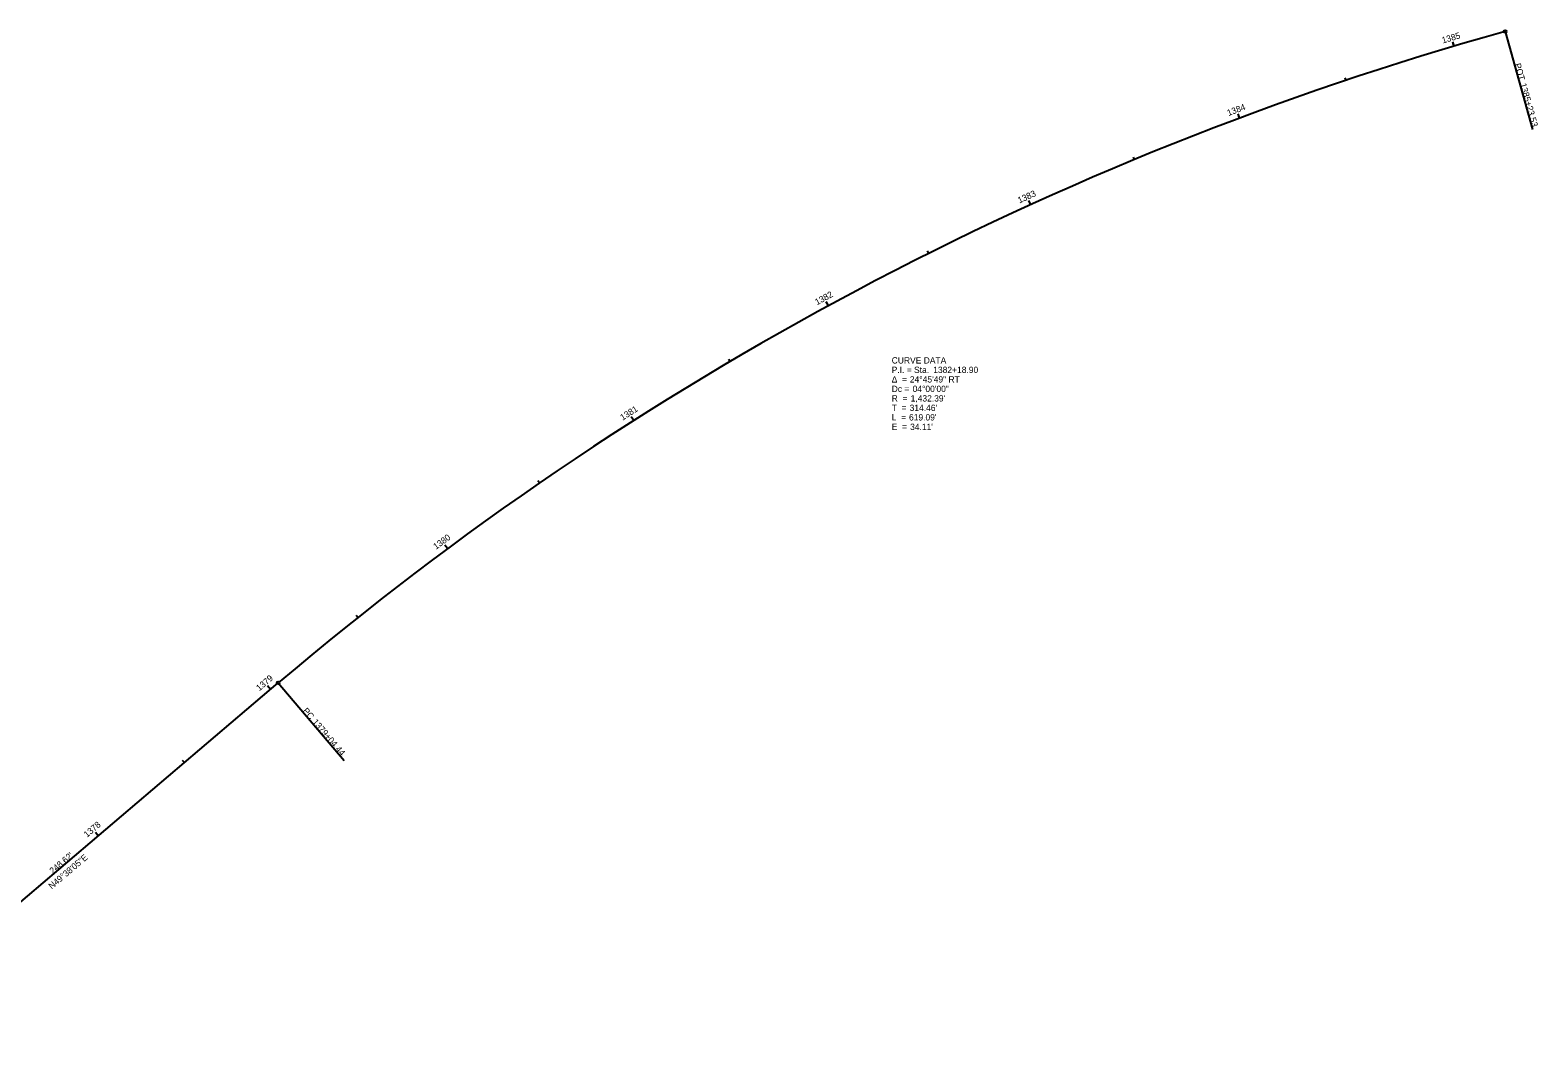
# Model space of a CAD drawing. Extents: x 155009 to 156350, y 371331 to 371956.
# Drawn here: x 155684 to 156350, y 371506 to 371956 of the extents above; entities that cross this region are included whole.
import ezdxf

# ---------------------------------------------------------------- set-up
doc = ezdxf.new("R2010")
doc.units = 0
for name, color, linetype in [('Default', 7, 'Continuous'), ('GE_X_Alignment', 7, 'Continuous'), ('GE_X_Alignment_1000_Curve_Data', 7, 'Continuous'), ('GE_X_Alignment_1000_Stations', 7, 'Continuous'), ('GE_X_Alignment_100_Curve_Data', 7, 'Continuous'), ('GE_X_Alignment_100_Stations', 7, 'Continuous'), ('GE_X_Alignment_500_Curve_Data', 7, 'Continuous'), ('GE_X_Alignment_500_Stations', 7, 'Continuous')]:
    doc.layers.add(name, color=color, linetype=linetype)

msp = doc.modelspace()

# ---------------------------------------------------------------- linework, layer by layer
at = {"layer": 'Default'}
msp.add_arc((156721.25, 370575.5), 1432.39, 105.6015, 130.36518, dxfattribs=at)
at = {"layer": 'GE_X_Alignment'}
msp.add_line((155604.12, 371505.86), (155793.55, 371666.88), dxfattribs=at)
msp.add_arc((156721.25, 370575.5), 1432.39, 105.6015, 130.36518, dxfattribs=at)
at = {"layer": 'GE_X_Alignment_1000_Stations'}
for p, q in [((156336.01, 371955.11), (156348.12, 371911.77)), ((156313.4, 371948.6), (156313.06, 371949.75)), ((155868.37, 371726.3), (155867.18, 371727.9)), ((155793.55, 371666.88), (155822.69, 371632.59))]:
    msp.add_line(p, q, dxfattribs=at)
for centre in [(156336.01, 371955.11), (155793.55, 371666.88)]:
    msp.add_circle(centre, 0.6, dxfattribs=at)
at = {"layer": 'GE_X_Alignment_100_Stations'}
for p, q in [((156336.01, 371955.11), (156348.12, 371911.77)), ((156313.4, 371948.6), (156312.83, 371950.51)), ((156265.73, 371933.53), (156265.35, 371934.66)), ((156218.61, 371916.8), (156217.91, 371918.68)), ((156172.11, 371898.44), (156171.65, 371899.55)), ((156126.27, 371878.47), (156125.44, 371880.29)), ((156081.16, 371856.92), (156080.63, 371857.99)), ((156036.83, 371833.8), (156035.88, 371835.55)), ((155993.33, 371809.14), (155992.72, 371810.18)), ((155950.72, 371782.99), (155949.65, 371784.67)), ((155909.05, 371755.36), (155908.37, 371756.35)), ((155868.37, 371726.3), (155867.18, 371727.9)), ((155828.73, 371695.83), (155827.98, 371696.77)), ((155793.55, 371666.88), (155822.69, 371632.59)), ((155790.17, 371664.01), (155788.87, 371665.53)), ((155752.07, 371631.62), (155751.29, 371632.54)), ((155713.97, 371599.24), (155712.68, 371600.76))]:
    msp.add_line(p, q, dxfattribs=at)
for centre in [(156336.01, 371955.11), (155793.55, 371666.88)]:
    msp.add_circle(centre, 0.6, dxfattribs=at)
at = {"layer": 'GE_X_Alignment_500_Stations'}
for p, q in [((156336.01, 371955.11), (156348.12, 371911.77)), ((156313.4, 371948.6), (156312.83, 371950.51)), ((156218.61, 371916.8), (156218.19, 371917.93)), ((156126.27, 371878.47), (156125.77, 371879.56)), ((156036.83, 371833.8), (156036.26, 371834.85)), ((155950.72, 371782.99), (155950.08, 371784)), ((155868.37, 371726.3), (155867.18, 371727.9)), ((155793.55, 371666.88), (155822.69, 371632.59)), ((155790.17, 371664.01), (155789.39, 371664.92)), ((155713.97, 371599.24), (155713.2, 371600.15))]:
    msp.add_line(p, q, dxfattribs=at)
for centre in [(156336.01, 371955.11), (155793.55, 371666.88)]:
    msp.add_circle(centre, 0.6, dxfattribs=at)

# ---------------------------------------------------------------- texts
at = {"layer": 'GE_X_Alignment_1000_Curve_Data'}
for s, p in [('CURVE DATA', (156064.78, 371808.2)), ('P.I. = Sta. ', (156064.78, 371804)), ('1382+18.90', (156083.15, 371804)), ('Δ  = ', (156064.78, 371799.8)), ('24°45\'49" RT', (156072.8, 371799.8)), ('Dc = ', (156064.78, 371795.6)), ('R  = ', (156064.78, 371791.4)), ("1,432.39'", (156073.15, 371791.4)), ('04°00\'00"', (156074.02, 371795.6)), ('T  = ', (156064.78, 371787.2)), ("314.46'", (156072.71, 371787.2)), ('L  = ', (156064.78, 371783)), ('E  = ', (156064.78, 371778.8)), ("619.09'", (156072.43, 371783)), ("34.11'", (156072.93, 371778.8))]:
    msp.add_text(s, height=2.8, dxfattribs=at).set_placement(p)
at = {"layer": 'GE_X_Alignment_1000_Stations'}
for s, rotation, p in [('POT', 285.6015, (156340.11, 371940.63)), ('1385+23.53', 285.6015, (156342.56, 371931.84)), ('1380', 36.54276, (155863.34, 371725.74)), ('PC', 310.36518, (155804.19, 371654.43)), ('1379+04.44', 310.36518, (155808.42, 371649.46)), ('N49°38\'05"E', 40.36518, (155693.42, 371575.47)), ("248.62'", 40.36518, (155693.86, 371582.21))]:
    msp.add_text(s, height=2.8, rotation=rotation, dxfattribs=at).set_placement(p)
at = {"layer": 'GE_X_Alignment_100_Curve_Data'}
for s, p in [('CURVE DATA', (156064.78, 371808.2)), ('P.I. = Sta. ', (156064.78, 371804)), ('1382+18.90', (156083.15, 371804)), ('Δ  = ', (156064.78, 371799.8)), ('24°45\'49" RT', (156072.8, 371799.8)), ('Dc = ', (156064.78, 371795.6)), ('R  = ', (156064.78, 371791.4)), ("1,432.39'", (156073.15, 371791.4)), ('04°00\'00"', (156074.02, 371795.6)), ('T  = ', (156064.78, 371787.2)), ("314.46'", (156072.71, 371787.2)), ('L  = ', (156064.78, 371783)), ('E  = ', (156064.78, 371778.8)), ("619.09'", (156072.43, 371783)), ("34.11'", (156072.93, 371778.8))]:
    msp.add_text(s, height=2.8, dxfattribs=at).set_placement(p)
at = {"layer": 'GE_X_Alignment_100_Stations'}
for s, rotation, p in [('1385', 16.5427, (156308.48, 371949.79)), ('POT', 285.6015, (156340.11, 371940.63)), ('1385+23.53', 285.6015, (156342.56, 371931.84)), ('1384', 20.54271, (156213.67, 371917.67)), ('1383', 24.54273, (156121.26, 371878.98)), ('1382', 28.54274, (156031.78, 371833.95)), ('1381', 32.54275, (155945.81, 371782.88)), ('1380', 36.54276, (155863.34, 371725.74)), ('1379', 40.36518, (155785.21, 371663.14)), ('PC', 310.36518, (155804.19, 371654.43)), ('1379+04.44', 310.36518, (155808.42, 371649.46)), ('1378', 40.36518, (155709, 371598.35)), ('N49°38\'05"E', 40.36518, (155693.42, 371575.47)), ("248.62'", 40.36518, (155693.86, 371582.21))]:
    msp.add_text(s, height=2.8, rotation=rotation, dxfattribs=at).set_placement(p)
at = {"layer": 'GE_X_Alignment_500_Curve_Data'}
for s, p in [('CURVE DATA', (156064.78, 371808.2)), ('P.I. = Sta. ', (156064.78, 371804)), ('1382+18.90', (156083.15, 371804)), ('Δ  = ', (156064.78, 371799.8)), ('24°45\'49" RT', (156072.8, 371799.8)), ('Dc = ', (156064.78, 371795.6)), ('R  = ', (156064.78, 371791.4)), ("1,432.39'", (156073.15, 371791.4)), ('04°00\'00"', (156074.02, 371795.6)), ('T  = ', (156064.78, 371787.2)), ("314.46'", (156072.71, 371787.2)), ('L  = ', (156064.78, 371783)), ('E  = ', (156064.78, 371778.8)), ("619.09'", (156072.43, 371783)), ("34.11'", (156072.93, 371778.8))]:
    msp.add_text(s, height=2.8, dxfattribs=at).set_placement(p)
at = {"layer": 'GE_X_Alignment_500_Stations'}
for s, rotation, p in [('1385', 16.5427, (156308.48, 371949.79)), ('POT', 285.6015, (156340.11, 371940.63)), ('1385+23.53', 285.6015, (156342.56, 371931.84)), ('1380', 36.54276, (155863.34, 371725.74)), ('PC', 310.36518, (155804.19, 371654.43)), ('1379+04.44', 310.36518, (155808.42, 371649.46)), ('N49°38\'05"E', 40.36518, (155693.42, 371575.47)), ("248.62'", 40.36518, (155693.86, 371582.21))]:
    msp.add_text(s, height=2.8, rotation=rotation, dxfattribs=at).set_placement(p)

doc.saveas('drawing.dxf')
